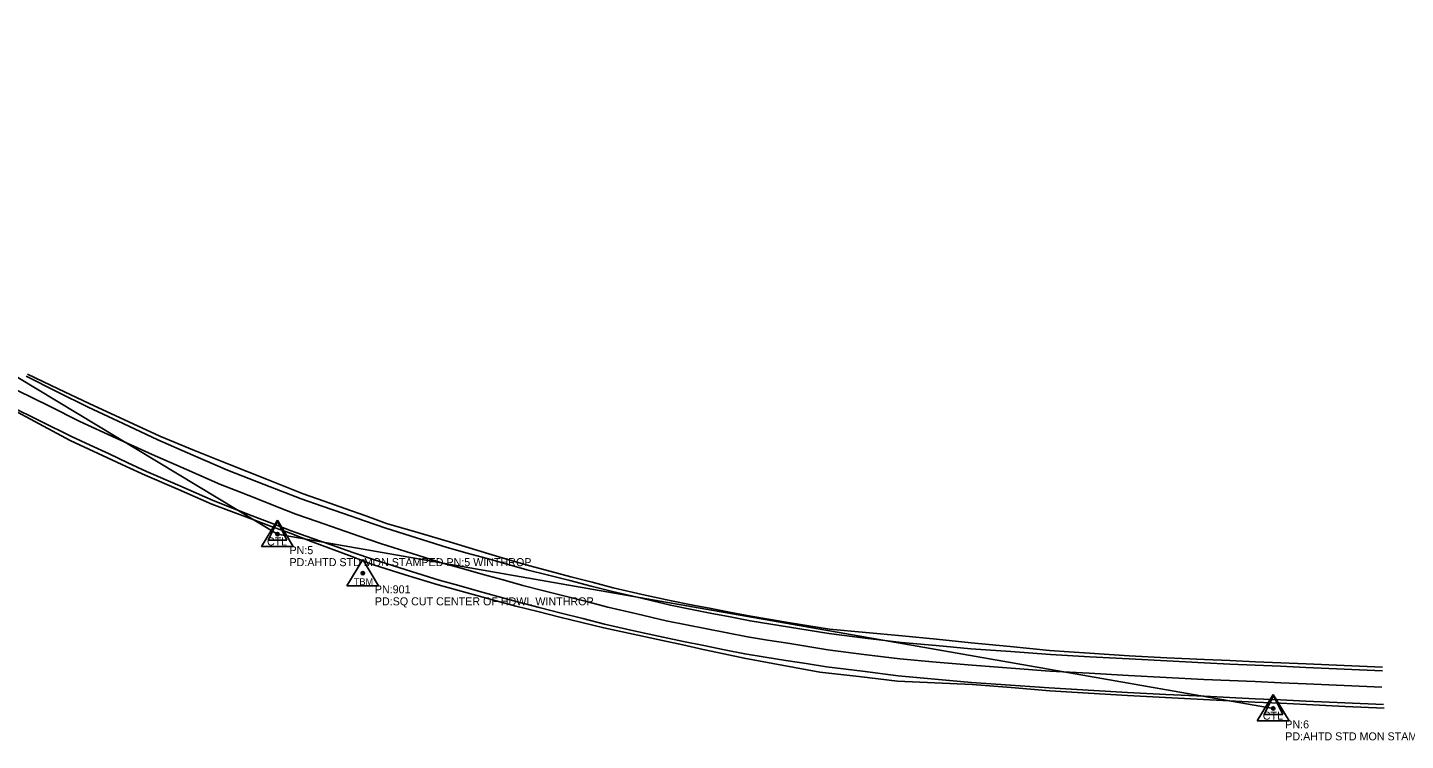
# Model space of a CAD drawing. Extents: x 592653 to 596268, y 1744647 to 1746025.
# Drawn here: x 594943 to 595804, y 1744717 to 1745163 of the extents above; entities that cross this region are included whole.
import ezdxf

# ---------------------------------------------------------------- set-up
doc = ezdxf.new("R2010")
doc.units = 0
for name, color, linetype in [('Default', 7, 'Continuous'), ('S_CAL_CORNER', 7, 'Continuous'), ('S_EDGE_PAVEMENT', 7, 'Continuous'), ('S_PAVEMENT_CROWN', 7, 'Continuous'), ('S_PRIMARY_CTL', 7, 'Continuous'), ('S_PRIMARY_CTL_ANNOT', 7, 'Continuous'), ('S_SHOULDER', 7, 'Continuous')]:
    doc.layers.add(name, color=color, linetype=linetype)

msp = doc.modelspace()

# ---------------------------------------------------------------- linework, layer by layer
at = {"layer": 'Default'}
for p, q in [((594574.34, 1745162.93), (595099.25, 1744846.3)), ((595099.25, 1744846.3), (595721.42, 1744737.44))]:
    msp.add_line(p, q, dxfattribs=at)
at = {"layer": 'S_CAL_CORNER'}
for p, q in [((595099.34, 1744854.28), (595093.46, 1744842.46)), ((595099.34, 1744854.28), (595105.15, 1744842.46)), ((595093.46, 1744842.46), (595105.15, 1744842.46)), ((595721.51, 1744745.42), (595715.64, 1744733.6)), ((595721.51, 1744745.42), (595727.33, 1744733.6)), ((595715.64, 1744733.6), (595727.33, 1744733.6))]:
    msp.add_line(p, q, dxfattribs=at)
at = {"layer": 'S_EDGE_PAVEMENT'}
for points in [[(594942.25, 1744944.97), (594961.56, 1744935.3), (594980.88, 1744925.64), (595002.74, 1744915.42), (595024.59, 1744905.2), (595046.32, 1744895.77), (595068.05, 1744886.35), (595091, 1744877.37), (595113.96, 1744868.39), (595127.19, 1744863.81), (595140.41, 1744859.22), (595153.64, 1744854.63), (595166.87, 1744850.05), (595186.08, 1744844.01), (595205.29, 1744837.97), (595217.75, 1744834.49), (595230.22, 1744831), (595242.68, 1744827.51), (595255.15, 1744824.03), (595268.53, 1744820.64), (595281.91, 1744817.26), (595295.29, 1744813.88), (595308.67, 1744810.5), (595326.7, 1744806.2), (595344.72, 1744801.91), (595357.18, 1744799.46), (595369.64, 1744797.01), (595382.09, 1744794.55), (595394.55, 1744792.1), (595419.11, 1744788.12), (595443.67, 1744784.13), (595466.43, 1744781.36), (595489.19, 1744778.59), (595510.87, 1744776.64), (595532.56, 1744774.7), (595557.35, 1744772.9), (595582.13, 1744771.1), (595606.76, 1744769.69), (595631.39, 1744768.28), (595654.85, 1744767.03), (595678.3, 1744765.78), (595694.19, 1744765.09), (595710.08, 1744764.41), (595725.98, 1744763.72), (595741.87, 1744763.03), (595765.75, 1744761.95), (595789.64, 1744760.87)], [(594931.8, 1744926.48), (594951.15, 1744916.95), (594970.5, 1744907.43), (594982.25, 1744901.93), (594994.01, 1744896.44), (595005.76, 1744890.94), (595017.51, 1744885.45), (595038.25, 1744876.43), (595058.99, 1744867.41), (595071.18, 1744862.63), (595083.37, 1744857.86), (595095.56, 1744853.08), (595107.75, 1744848.3), (595120.61, 1744843.82), (595133.46, 1744839.34), (595146.32, 1744834.86), (595159.17, 1744830.38), (595179.73, 1744823.97), (595200.28, 1744817.55), (595212.53, 1744814.15), (595224.78, 1744810.75), (595237.02, 1744807.35), (595249.27, 1744803.95), (595262.83, 1744800.47), (595276.4, 1744796.99), (595289.96, 1744793.52), (595303.52, 1744790.04), (595321.83, 1744785.96), (595340.13, 1744781.88), (595352.91, 1744779.27), (595365.68, 1744776.67), (595378.45, 1744774.06), (595391.23, 1744771.46), (595404, 1744769.44), (595416.77, 1744767.42), (595429.54, 1744765.41), (595442.31, 1744763.39), (595464.7, 1744760.6), (595487.1, 1744757.8), (595510.01, 1744755.67), (595532.93, 1744753.54), (595557.18, 1744751.85), (595581.43, 1744750.16), (595605.85, 1744748.78), (595630.27, 1744747.39), (595654.25, 1744746.17), (595678.22, 1744744.96), (595694.13, 1744744.19), (595710.04, 1744743.43), (595725.95, 1744742.66), (595741.86, 1744741.9), (595766.04, 1744740.89), (595790.21, 1744739.88)]]:
    msp.add_lwpolyline(points, dxfattribs=at)
at = {"layer": 'S_PAVEMENT_CROWN'}
msp.add_lwpolyline([(594936.82, 1744936.18), (594956.29, 1744926.49), (594975.75, 1744916.8), (594998.36, 1744906.4), (595020.97, 1744896), (595042.35, 1744886.69), (595063.74, 1744877.38), (595075.49, 1744872.75), (595087.25, 1744868.12), (595099, 1744863.48), (595110.76, 1744858.85), (595123.95, 1744854.23), (595137.15, 1744849.62), (595150.34, 1744845), (595163.54, 1744840.39), (595183.37, 1744834.23), (595203.2, 1744828.06), (595215.52, 1744824.62), (595227.85, 1744821.18), (595240.17, 1744817.73), (595252.5, 1744814.29), (595265.77, 1744810.9), (595279.03, 1744807.51), (595292.3, 1744804.12), (595305.57, 1744800.73), (595323.87, 1744796.48), (595342.17, 1744792.23), (595354.86, 1744789.72), (595367.55, 1744787.21), (595380.24, 1744784.7), (595392.93, 1744782.18), (595405.49, 1744780.14), (595418.05, 1744778.1), (595430.62, 1744776.07), (595443.18, 1744774.03), (595465.67, 1744771.17), (595488.16, 1744768.32), (595510.75, 1744766.35), (595533.34, 1744764.38), (595557.63, 1744762.55), (595581.92, 1744760.71), (595606.44, 1744759.37), (595630.95, 1744758.02), (595654.53, 1744756.78), (595678.11, 1744755.54), (595694.1, 1744754.84), (595710.08, 1744754.14), (595726.07, 1744753.44), (595742.05, 1744752.74), (595765.68, 1744751.68), (595789.3, 1744750.61)], dxfattribs=at)
at = {"layer": 'S_PRIMARY_CTL'}
for p, q in [((595099.25, 1744855), (595089.21, 1744838.49)), ((595099.25, 1744855), (595089.21, 1744838.49)), ((595099.25, 1744855), (595109.07, 1744838.49)), ((595099.25, 1744855), (595109.07, 1744838.49)), ((595089.21, 1744838.49), (595109.07, 1744838.49)), ((595089.21, 1744838.49), (595109.07, 1744838.49)), ((595152.58, 1744830.53), (595142.55, 1744814.02)), ((595152.58, 1744830.53), (595142.55, 1744814.02)), ((595152.58, 1744830.53), (595162.41, 1744814.02)), ((595152.58, 1744830.53), (595162.41, 1744814.02)), ((595142.55, 1744814.02), (595162.41, 1744814.02)), ((595142.55, 1744814.02), (595162.41, 1744814.02)), ((595721.42, 1744746.14), (595711.39, 1744729.63)), ((595721.42, 1744746.14), (595711.39, 1744729.63)), ((595721.42, 1744746.14), (595731.25, 1744729.63)), ((595721.42, 1744746.14), (595731.25, 1744729.63)), ((595711.39, 1744729.63), (595731.25, 1744729.63)), ((595711.39, 1744729.63), (595731.25, 1744729.63))]:
    msp.add_line(p, q, dxfattribs=at)
for centre, radius in [((595099.25, 1744846.3), 1.04), ((595099.25, 1744846.3), 1.04), ((595099.25, 1744846.3), 0.609), ((595099.25, 1744846.3), 0.609), ((595099.25, 1744846.3), 0.344), ((595099.25, 1744846.3), 0.344), ((595152.58, 1744821.83), 1.04), ((595152.58, 1744821.83), 1.04), ((595152.58, 1744821.83), 0.609), ((595152.58, 1744821.83), 0.609), ((595152.58, 1744821.83), 0.344), ((595152.58, 1744821.83), 0.344), ((595721.42, 1744737.44), 1.04), ((595721.42, 1744737.44), 1.04), ((595721.42, 1744737.44), 0.609), ((595721.42, 1744737.44), 0.609), ((595721.42, 1744737.44), 0.344), ((595721.42, 1744737.44), 0.344)]:
    msp.add_circle(centre, radius, dxfattribs=at)
at = {"layer": 'S_SHOULDER'}
for points in [[(594943.05, 1744946.4), (594962.3, 1744937.2), (594981.56, 1744927.99), (595003.63, 1744917.74), (595025.69, 1744907.49), (595047.48, 1744898.65), (595069.27, 1744889.81), (595092.33, 1744880.68), (595115.39, 1744871.56), (595128.39, 1744866.92), (595141.39, 1744862.29), (595154.39, 1744857.66), (595167.39, 1744853.02), (595187.01, 1744847.26), (595206.63, 1744841.51), (595219.01, 1744837.78), (595231.39, 1744834.06), (595243.78, 1744830.34), (595256.16, 1744826.62), (595269.37, 1744823.16), (595282.58, 1744819.7), (595295.8, 1744816.24), (595309.01, 1744812.78), (595327.19, 1744808.68), (595345.36, 1744804.59), (595357.79, 1744802.2), (595370.21, 1744799.8), (595382.64, 1744797.41), (595395.06, 1744795.02), (595419.61, 1744790.98), (595444.16, 1744786.94), (595466.84, 1744784.81), (595489.51, 1744782.67), (595511.06, 1744780.57), (595532.61, 1744778.47), (595557.06, 1744776.05), (595581.51, 1744773.62), (595594, 1744772.79), (595606.5, 1744771.97), (595618.99, 1744771.14), (595631.48, 1744770.32), (595654.98, 1744769.1), (595678.47, 1744767.87), (595694.35, 1744767.24), (595710.23, 1744766.61), (595726.1, 1744765.98), (595741.98, 1744765.35), (595765.79, 1744764.26), (595789.6, 1744763.17)], [(594931.03, 1744925.69), (594950.32, 1744915.24), (594969.62, 1744904.8), (594981.35, 1744899.41), (594993.08, 1744894.03), (595004.81, 1744888.64), (595016.53, 1744883.25), (595037.43, 1744874.12), (595058.32, 1744864.98), (595070.52, 1744860.45), (595082.71, 1744855.91), (595094.91, 1744851.37), (595107.11, 1744846.84), (595119.98, 1744841.98), (595132.86, 1744837.12), (595145.74, 1744832.27), (595158.62, 1744827.41), (595179.12, 1744820.98), (595199.62, 1744814.56), (595211.74, 1744811.24), (595223.85, 1744807.91), (595235.96, 1744804.59), (595248.07, 1744801.27), (595261.82, 1744797.89), (595275.57, 1744794.51), (595289.31, 1744791.12), (595303.06, 1744787.74), (595321.41, 1744783.77), (595339.75, 1744779.79), (595352.52, 1744777.03), (595365.28, 1744774.26), (595378.04, 1744771.5), (595390.81, 1744768.73), (595414.44, 1744764.43), (595438.08, 1744760.12), (595462.4, 1744757.25), (595486.71, 1744754.37), (595510.03, 1744753.38), (595533.35, 1744752.39), (595557.59, 1744750.39), (595581.84, 1744748.39), (595606.04, 1744746.88), (595630.25, 1744745.37), (595653.99, 1744744.17), (595677.74, 1744742.98), (595693.84, 1744742.18), (595709.93, 1744741.38), (595726.03, 1744740.59), (595742.12, 1744739.79), (595766.44, 1744738.68), (595790.75, 1744737.58)]]:
    msp.add_lwpolyline(points, dxfattribs=at)

# ---------------------------------------------------------------- texts
at = {"layer": 'S_PRIMARY_CTL'}
for s, height, p in [('CTL', 5, (595092.66, 1744839.22)), ('CTL', 5, (595092.66, 1744839.22)), ('TBM', 4.287, (595146.93, 1744814.44)), ('TBM', 4.287, (595146.93, 1744814.44)), ('CTL', 5, (595714.84, 1744730.37)), ('CTL', 5, (595714.84, 1744730.37))]:
    msp.add_text(s, height=height, rotation=360, dxfattribs=at).set_placement(p)
at = {"layer": 'S_PRIMARY_CTL_ANNOT'}
for s, p in [('PN:5', (595106.75, 1744833.8)), ('PD:AHTD STD MON STAMPED PN:5 WINTHROP', (595106.75, 1744826.3)), ('PN:901', (595160.08, 1744809.33)), ('PD:SQ CUT CENTER OF HDWL WINTHROP', (595160.08, 1744801.83)), ('PN:6', (595728.92, 1744724.94)), ('PD:AHTD STD MON STAMPED PN:6 WINTHROP', (595728.92, 1744717.44))]:
    msp.add_text(s, height=5, dxfattribs=at).set_placement(p)

doc.saveas('drawing.dxf')
